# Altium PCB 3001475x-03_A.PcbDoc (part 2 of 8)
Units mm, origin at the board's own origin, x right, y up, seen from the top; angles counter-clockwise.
Board outline 100 x 72 mm, 12 copper layers (Top Layer, L2 GND, Layer 3, L4 GND, Layer 5, L6 PWR, L7 3V3, Layer 8, L9 GND, Layer 10, L11 GND, Bottom Layer), stack 1.735 mm thick; 428 components, 499 nets, 1973 pads, 1473 vias.
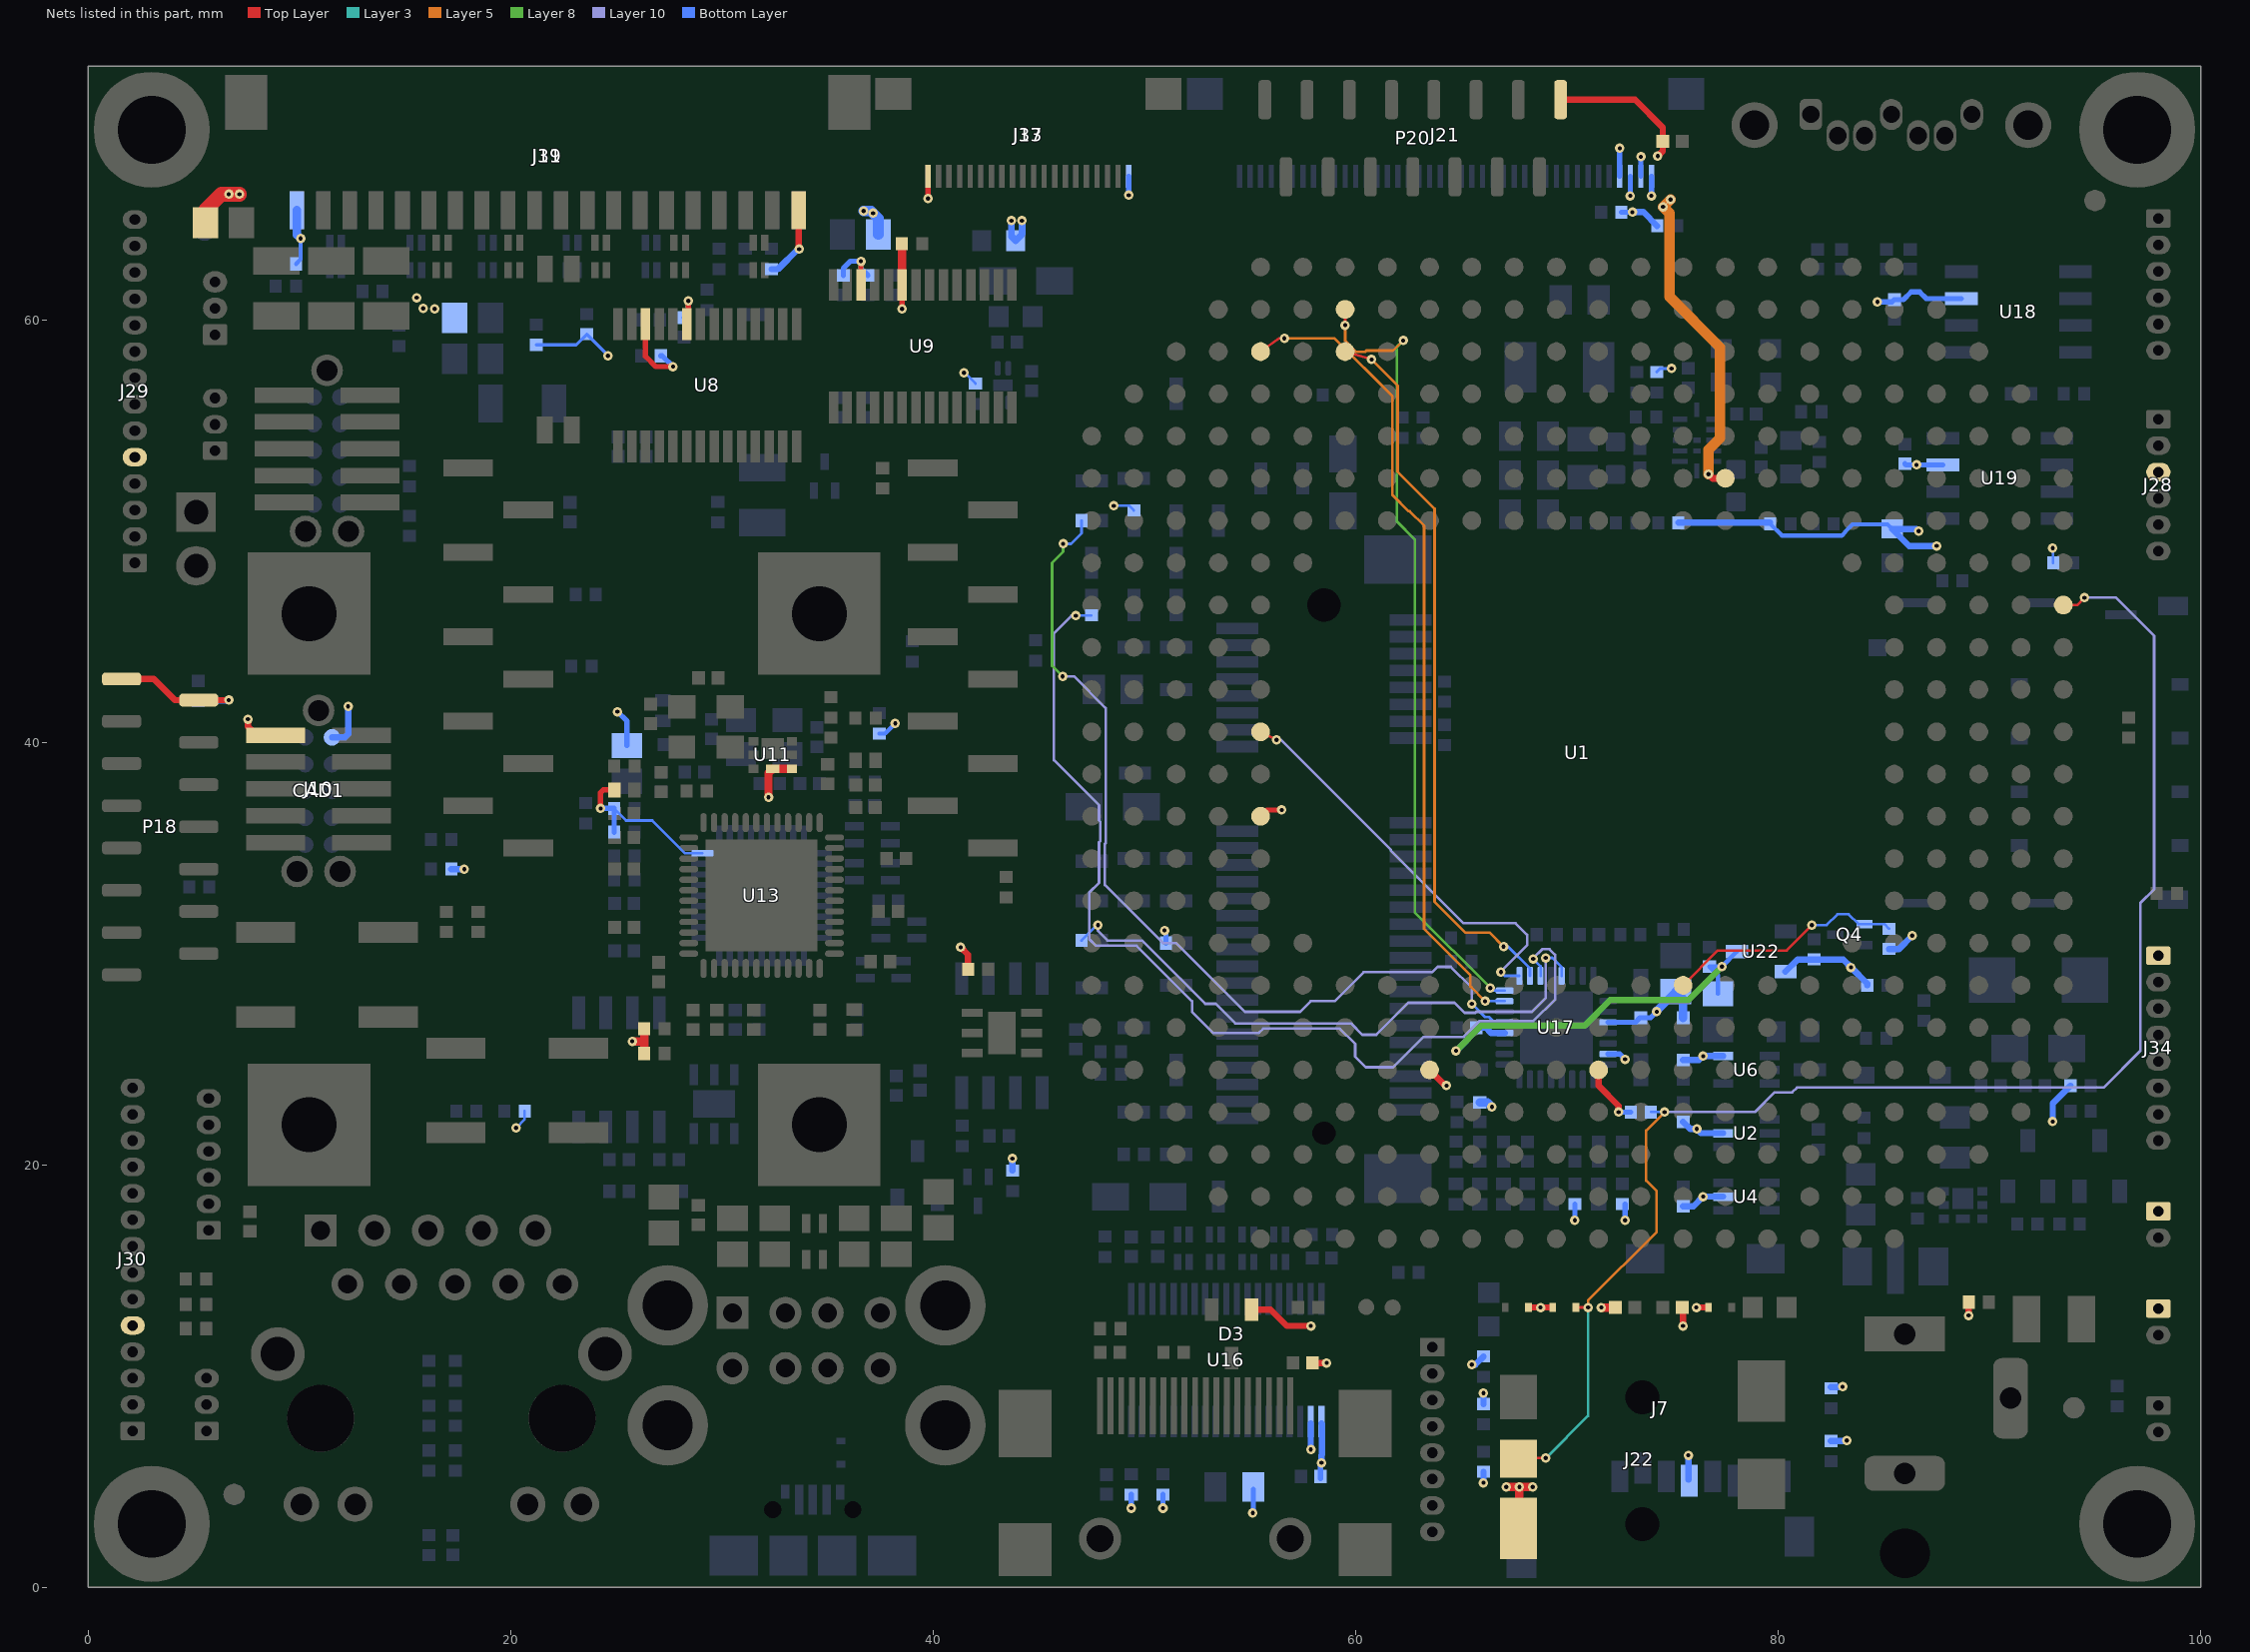
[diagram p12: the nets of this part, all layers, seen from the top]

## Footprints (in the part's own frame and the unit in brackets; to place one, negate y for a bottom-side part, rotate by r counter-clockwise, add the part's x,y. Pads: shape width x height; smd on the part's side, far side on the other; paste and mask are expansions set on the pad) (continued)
KYCON_KUSBX-AS2N [mil]
  rect 60x60 hole 35: A1(0,0)
  round 60 hole 35: A2(98.43,0) A4(275.59,0) B1(0,-103.15) B2(98.43,-103.15) B3(177.17,-103.15) B4(275.59,-103.15)
  round 60 / inner oval 60x53.15 / far side round 60 hole 35: A3(177.17,0)
  round 150 hole 93: SH1(-120.87,-209.84) SH2(-120.87,13.78) SH3(396.46,-209.84) SH4(396.46,13.78)
  body extent -171,-633 446,56, height 634
LABEL_10x10 [mm]
  silkscreen extent -5.08,-5.08 5.08,5.08
LEDM3020X130N [mm]
  rect 1.3x2.2 smd: A(-1.3,0) K(1.3,0)
  body extent -1.6,-1.1 1.6,1.1, height 1.5
MH_185_125_NP [mm]
  round 3.175 hole 3.175 unplated: 1(0,0)
  Keep-Out Layer circle w0.102: c0,0 r2.349
MODULE_CCWMX6 [mil]
  round 35 smd: A5(-590.55,905.51) A6(-511.81,905.51) A7(-433.07,905.51) A8(-354.33,905.51) A9(-275.59,905.51) A10(-196.85,905.51) A11(-118.11,905.51) A12(-39.37,905.51) A13(39.37,905.51) A14(118.11,905.51) A15(196.85,905.51) A16(275.59,905.51) A17(354.33,905.51) A18(433.07,905.51) A19(511.81,905.51) A20(590.55,905.51) AA2(-826.77,-669.29) AA3(-748.03,-669.29) AA4(-669.29,-669.29) AA5(-590.55,-669.29) AA6(-511.81,-669.29) AA7(-433.07,-669.29) AA8(-354.33,-669.29) AA9(-275.59,-669.29) AA10(-196.85,-669.29) AA11(-118.11,-669.29) AA12(-39.37,-669.29) AA13(39.37,-669.29) AA14(118.11,-669.29) AA15(196.85,-669.29) AA16(275.59,-669.29) AA17(354.33,-669.29) AA18(433.07,-669.29) AA19(511.81,-669.29) AA20(590.55,-669.29) AA21(669.29,-669.29) AA22(748.03,-669.29) AA23(826.77,-669.29) AB3(-748.03,-748.03) AB4(-669.29,-748.03) AB5(-590.55,-748.03) AB6(-511.81,-748.03) AB7(-433.07,-748.03) AB8(-354.33,-748.03) AB9(-275.59,-748.03) AB10(-196.85,-748.03) AB11(-118.11,-748.03) AB12(-39.37,-748.03) AB13(39.37,-748.03) AB14(118.11,-748.03) AB15(196.85,-748.03) AB16(275.59,-748.03) AB17(354.33,-748.03) AB18(433.07,-748.03) AB19(511.81,-748.03) AB20(590.55,-748.03) AB21(669.29,-748.03) AB22(748.03,-748.03) AC4(-669.29,-826.77) AC5(-590.55,-826.77) AC6(-511.81,-826.77) AC7(-433.07,-826.77) AC8(-354.33,-826.77) AC9(-275.59,-826.77) AC10(-196.85,-826.77) AC11(-118.11,-826.77) AC12(-39.37,-826.77) AC13(39.37,-826.77) AC14(118.11,-826.77) AC15(196.85,-826.77) AC16(275.59,-826.77) AC17(354.33,-826.77) AC18(433.07,-826.77) AC19(511.81,-826.77) AC20(590.55,-826.77) AC21(669.29,-826.77) AD5(-590.55,-905.51) AD6(-511.81,-905.51) AD7(-433.07,-905.51) AD8(-354.33,-905.51) AD9(-275.59,-905.51) AD10(-196.85,-905.51) AD11(-118.11,-905.51) AD12(-39.37,-905.51) AD13(39.37,-905.51) AD14(118.11,-905.51) AD15(196.85,-905.51) AD16(275.59,-905.51) AD17(354.33,-905.51) AD18(433.07,-905.51) AD19(511.81,-905.51) AD20(590.55,-905.51) B4(-669.29,826.77) B5(-590.55,826.77) B6(-511.81,826.77) B7(-433.07,826.77) B8(-354.33,826.77) B9(-275.59,826.77) B10(-196.85,826.77) B11(-118.11,826.77) B12(-39.37,826.77) B13(39.37,826.77) B14(118.11,826.77) B15(196.85,826.77) B16(275.59,826.77) B17(354.33,826.77) B18(433.07,826.77) B19(511.81,826.77) B20(590.55,826.77) B21(669.29,826.77) C3(-748.03,748.03) C4(-669.29,748.03) C5(-590.55,748.03) C6(-511.81,748.03) C7(-433.07,748.03) C8(-354.33,748.03) C9(-275.59,748.03) C10(-196.85,748.03) C11(-118.11,748.03) C12(-39.37,748.03) C13(39.37,748.03) C14(118.11,748.03) C15(196.85,748.03) C16(275.59,748.03) C17(354.33,748.03) C18(433.07,748.03) C19(511.81,748.03) C20(590.55,748.03) C21(669.29,748.03) C22(748.03,748.03) D2(-826.77,669.29) D3(-748.03,669.29) D4(-669.29,669.29) D5(-590.55,669.29) D6(-511.81,669.29) D7(-433.07,669.29) D8(-354.33,669.29) D9(-275.59,669.29) D10(-196.85,669.29) D11(-118.11,669.29) D12(-39.37,669.29) D13(39.37,669.29) D14(118.11,669.29) D15(196.85,669.29) D16(275.59,669.29) D17(354.33,669.29) D18(433.07,669.29) D19(511.81,669.29) D20(590.55,669.29) D21(669.29,669.29) D22(748.03,669.29) D23(826.77,669.29) E1(-905.51,590.55) E2(-826.77,590.55) E3(-748.03,590.55) E4(-669.29,590.55) E5(-590.55,590.55) E6(-511.81,590.55) E7(-433.07,590.55) E8(-354.33,590.55) E9(-275.59,590.55) E10(-196.85,590.55) E11(-118.11,590.55) E12(-39.37,590.55) E13(39.37,590.55) E14(118.11,590.55) E15(196.85,590.55) E16(275.59,590.55) E17(354.33,590.55) E18(433.07,590.55) E19(511.81,590.55) E20(590.55,590.55) E21(669.29,590.55) E22(748.03,590.55) E23(826.77,590.55) E24(905.51,590.55) F1(-905.51,511.81) F2(-826.77,511.81) F3(-748.03,511.81) F4(-669.29,511.81) F5(-590.55,511.81) F6(-511.81,511.81) F7(-433.07,511.81) F8(-354.33,511.81) F9(-275.59,511.81) F10(-196.85,511.81) F11(-118.11,511.81) F12(-39.37,511.81) F13(39.37,511.81) F14(118.11,511.81) F15(196.85,511.81) F16(275.59,511.81) F17(354.33,511.81) F18(433.07,511.81) F19(511.81,511.81) F20(590.55,511.81) F21(669.29,511.81) F22(748.03,511.81) F23(826.77,511.81) F24(905.51,511.81) G1(-905.51,433.07) G2(-826.77,433.07) G3(-748.03,433.07) G4(-669.29,433.07) G5(-590.55,433.07) G6(-511.81,433.07) G7(-433.07,433.07) G8(-354.33,433.07) G9(-275.59,433.07) G10(-196.85,433.07) G11(-118.11,433.07) G12(-39.37,433.07) G13(39.37,433.07) G14(118.11,433.07) G15(196.85,433.07) G16(275.59,433.07) G17(354.33,433.07) G18(433.07,433.07) G19(511.81,433.07) G20(590.55,433.07) G21(669.29,433.07) G22(748.03,433.07) G23(826.77,433.07) G24(905.51,433.07) H1(-905.51,354.33) H2(-826.77,354.33) H3(-748.03,354.33) H4(-669.29,354.33) H5(-590.55,354.33) H6(-511.81,354.33) H19(511.81,354.33) H20(590.55,354.33) H21(669.29,354.33) H22(748.03,354.33) H23(826.77,354.33) H24(905.51,354.33) J1(-905.51,275.59) J2(-826.77,275.59) J3(-748.03,275.59) J4(-669.29,275.59) J5(-590.55,275.59) J20(590.55,275.59) J21(669.29,275.59) J22(748.03,275.59) J23(826.77,275.59) J24(905.51,275.59) K1(-905.51,196.85) K2(-826.77,196.85) K3(-748.03,196.85) K4(-669.29,196.85) K5(-590.55,196.85) K20(590.55,196.85) K21(669.29,196.85) K22(748.03,196.85) K23(826.77,196.85) K24(905.51,196.85) L1(-905.51,118.11) L2(-826.77,118.11) L3(-748.03,118.11) L4(-669.29,118.11) L5(-590.55,118.11) L20(590.55,118.11) L21(669.29,118.11) L22(748.03,118.11) L23(826.77,118.11) L24(905.51,118.11) M1(-905.51,39.37) M2(-826.77,39.37) M3(-748.03,39.37) M4(-669.29,39.37) M5(-590.55,39.37) M20(590.55,39.37) M21(669.29,39.37) M22(748.03,39.37) M23(826.77,39.37) M24(905.51,39.37) N1(-905.51,-39.37) N2(-826.77,-39.37) N3(-748.03,-39.37) N4(-669.29,-39.37) N5(-590.55,-39.37) N20(590.55,-39.37) N21(669.29,-39.37) N22(748.03,-39.37) N23(826.77,-39.37) N24(905.51,-39.37) P1(-905.51,-118.11) P2(-826.77,-118.11) P3(-748.03,-118.11) P4(-669.29,-118.11) P5(-590.55,-118.11) P20(590.55,-118.11) P21(669.29,-118.11) P22(748.03,-118.11) P23(826.77,-118.11) P24(905.51,-118.11) R1(-905.51,-196.85) R2(-826.77,-196.85) R3(-748.03,-196.85) R4(-669.29,-196.85) R5(-590.55,-196.85) R20(590.55,-196.85) R21(669.29,-196.85) R22(748.03,-196.85) R23(826.77,-196.85) R24(905.51,-196.85) T1(-905.51,-275.59) T2(-826.77,-275.59) T3(-748.03,-275.59) T4(-669.29,-275.59) T5(-590.55,-275.59) T20(590.55,-275.59) T21(669.29,-275.59) T22(748.03,-275.59) T23(826.77,-275.59) T24(905.51,-275.59) U1(-905.51,-354.33) U2(-826.77,-354.33) U3(-748.03,-354.33) U4(-669.29,-354.33) U5(-590.55,-354.33) U6(-511.81,-354.33) U19(511.81,-354.33) U20(590.55,-354.33) U21(669.29,-354.33) U22(748.03,-354.33) U23(826.77,-354.33) U24(905.51,-354.33) V1(-905.51,-433.07) V2(-826.77,-433.07) V3(-748.03,-433.07) V4(-669.29,-433.07) V5(-590.55,-433.07) V6(-511.81,-433.07) V7(-433.07,-433.07) V8(-354.33,-433.07) V9(-275.59,-433.07) V10(-196.85,-433.07) V11(-118.11,-433.07) V12(-39.37,-433.07) V13(39.37,-433.07) V14(118.11,-433.07) V15(196.85,-433.07) V16(275.59,-433.07) V17(354.33,-433.07) V18(433.07,-433.07) V19(511.81,-433.07) V20(590.55,-433.07) V21(669.29,-433.07) V22(748.03,-433.07) V23(826.77,-433.07) V24(905.51,-433.07) W1(-905.51,-511.81) W2(-826.77,-511.81) W3(-748.03,-511.81) W4(-669.29,-511.81) W5(-590.55,-511.81) W6(-511.81,-511.81) W7(-433.07,-511.81) W8(-354.33,-511.81) W9(-275.59,-511.81) W10(-196.85,-511.81) W11(-118.11,-511.81) W12(-39.37,-511.81) W13(39.37,-511.81) W14(118.11,-511.81) W15(196.85,-511.81) W16(275.59,-511.81) W17(354.33,-511.81) W18(433.07,-511.81) W19(511.81,-511.81) W20(590.55,-511.81) W21(669.29,-511.81) W22(748.03,-511.81) W23(826.77,-511.81) W24(905.51,-511.81) Y1(-905.51,-590.55) Y2(-826.77,-590.55) Y3(-748.03,-590.55) Y4(-669.29,-590.55) Y5(-590.55,-590.55) Y6(-511.81,-590.55) Y7(-433.07,-590.55) Y8(-354.33,-590.55) Y9(-275.59,-590.55) Y10(-196.85,-590.55) Y11(-118.11,-590.55) Y12(-39.37,-590.55) Y13(39.37,-590.55) Y14(118.11,-590.55) Y15(196.85,-590.55) Y16(275.59,-590.55) Y17(354.33,-590.55) Y18(433.07,-590.55) Y19(511.81,-590.55) Y20(590.55,-590.55) Y21(669.29,-590.55) Y22(748.03,-590.55) Y23(826.77,-590.55) Y24(905.51,-590.55)
  silkscreen extent -984,-984 984,984, body extent -984,-984 984,984, height 220
MOLEX_53047-0210 [mm]
  rrect20% 0.875x1.15 hole 0.5: 1(0,0)
  oval 0.875x1.15 hole 0.5: 2(1.25,0)
  body extent -1.52,-1.15 2.73,2.05, height 4.2
MOLEX_53047-0310#1 [mm]
  rrect20% 1x1.15 hole 0.5: 1(0,0)
  oval 1x1.15 hole 0.5: 2(1.25,0) 3(2.5,0)
  body extent -1.5,-1.15 4,2.05, height 4.2
MOLEX_53047-0310#2 [mm]
  rrect20% 0.875x1.15 hole 0.5: 1(0,0)
  oval 0.875x1.15 hole 0.5: 2(1.25,0) 3(2.5,0)
  body extent -1.5,-1.15 4,2.05, height 4.2
MOLEX_53047-0610 [mm]
  rrect20% 0.875x1.15 hole 0.5: 1(0,0)
  oval 0.875x1.15 hole 0.5: 2(1.25,0) 3(2.5,0) 4(3.75,0) 5(5,0) 6(6.25,0)
  body extent -1.5,-1.15 7.75,2.05, height 4.2
MOLEX_53047-0810#1 [mm]
  rect 0.875x1.15 hole 0.5: 1(0,0)
  oval 0.875x1.15 hole 0.5: 2(1.25,0) 3(2.5,0) 4(3.75,0) 5(5,0) 6(6.25,0) 7(7.5,0) 8(8.75,0)
  body extent -1.5,-1.15 10.25,2.05, height 4.2
MOLEX_53047-0810#2 [mm]
  rrect20% 0.875x1.15 hole 0.5: 1(0,0)
  oval 0.875x1.15 hole 0.5: 2(1.25,0) 3(2.5,0) 4(3.75,0) 5(5,0) 6(6.25,0) 7(7.5,0) 8(8.75,0)
  body extent -1.5,-1.15 10.25,2.05, height 4.2
MOLEX_53047-1410 [mm]
  rrect20% 0.875x1.15 hole 0.5: 1(0,0)
  oval 0.875x1.15 hole 0.5: 2(1.25,0) 3(2.5,0) 4(3.75,0) 5(5,0) 6(6.25,0) 7(7.5,0) 8(8.75,0) 9(10,0) 10(11.25,0) 11(12.5,0) 12(13.75,0) 13(15,0) 14(16.25,0)
  body extent -1.5,-1.15 17.75,2.05, height 4.2
MOLEX_78727-0001 [mm]
  rect 0.8x0.6 smd: 1(0.33,4.38) 2(0.33,1.84) 3(0.33,-0.7) 4(0.33,-3.24) 5(-7.29,4.38) 6(-7.29,1.84) 7(-7.29,-0.7) 8(-7.29,-3.24)
  rect 0.85x0.8 smd: 9(-13.99,-4.98)
  rect 1.5x0.42 smd: 10(-2.47,-6.54) 12(-6.35,7.11) 13(-12.21,7.11) 14(-12.21,-7.11) 15(-6.35,-7.11)
  rect 1.4x0.87 smd: 11(0,6.95) 16(0,-6.95)
  body extent -14.53,-7.26 0.69,7.27, height 1.4
MOLEX_500873-0806 [mm]
  rect 0.8x1.5 smd: 1(0,0) 2(1.1,-0.4) 3(2.2,0) 4(3.3,0.2) 5(4.4,0) 6(5.5,0.2) 7(6.6,0) 8(7.7,0)
  rect 1.8x1.4 smd: 9(1.2,-10.3) 10(6.9,-10.3)
  rect 1.4x1.9 smd: 11(8.5,2.85) 12(-4.65,3.85)
  body extent -5.05,-10.7 8.95,4.5, height 1.87
omron_xf2m-2015-1a [mm]
  rect 0.25x1.1 smd: 1(-4.75,1.95) 2(-4.25,1.95) 3(-3.75,1.95) 4(-3.25,1.95) 5(-2.75,1.95) 6(-2.25,1.95) 7(-1.75,1.95) 8(-1.25,1.95) 9(-0.75,1.95) 10(-0.25,1.95) 11(0.25,1.95) 12(0.75,1.95) 13(1.25,1.95) 14(1.75,1.95) 15(2.25,1.95) 16(2.75,1.95) 17(3.25,1.95) 18(3.75,1.95) 19(4.25,1.95) 20(4.75,1.95)
  rect 1.7x1.5 smd: M1(6.4,-1.95) M2(-6.4,-1.95)
  body extent -7.05,-2.9 7.05,3.3, height 2.18
OMRON_XF2M-4015-1A [mm]
  rect 0.25x1.1 smd: 1(-9.75,1.95) 2(-9.25,1.95) 3(-8.75,1.95) 4(-8.25,1.95) 5(-7.75,1.95) 6(-7.25,1.95) 7(-6.75,1.95) 8(-6.25,1.95) 9(-5.75,1.95) 10(-5.25,1.95) 11(-4.75,1.95) 12(-4.25,1.95) 13(-3.75,1.95) 14(-3.25,1.95) 15(-2.75,1.95) 16(-2.25,1.95) 17(-1.75,1.95) 18(-1.25,1.95) 19(-0.75,1.95) 20(-0.25,1.95) 21(0.25,1.95) 22(0.75,1.95) 23(1.25,1.95) 24(1.75,1.95) 25(2.25,1.95) 26(2.75,1.95) 27(3.25,1.95) 28(3.75,1.95) 29(4.25,1.95) 30(4.75,1.95) 31(5.25,1.95) 32(5.75,1.95) 33(6.25,1.95) 34(6.75,1.95) 35(7.25,1.95) 36(7.75,1.95) 37(8.25,1.95) 38(8.75,1.95) 39(9.25,1.95) 40(9.75,1.95)
  rect 1.7x1.5 smd: M1(11.4,-1.95) M2(-11.4,-1.95)
  body extent -12.05,-2.9 12.05,3.3, height 2.18
OSC210P320X250X90-4N [mm]
  rect 1.25x1.1 smd: 1(-1.15,-0.95)
  rect 1.3x1.1 smd: 2(1.15,-0.95) 3(1.15,0.95) 4(-1.15,0.95)
  body extent -1.63,-1.3 1.62,1.3, height 0.6
PCBNUMBER [mm]
QFN50P500X500X100-33CN [mm]
  rrect50% 0.85x0.3 smd: 1(-2.45,1.75) 2(-2.45,1.25) 3(-2.45,0.75) 4(-2.45,0.25) 5(-2.45,-0.25) 6(-2.45,-0.75) 7(-2.45,-1.25) 8(-2.45,-1.75) 17(2.45,-1.75) 18(2.45,-1.25) 19(2.45,-0.75) 20(2.45,-0.25) 21(2.45,0.25) 22(2.45,0.75) 23(2.45,1.25) 24(2.45,1.75)
  rrect50% 0.3x0.85 smd: 9(-1.75,-2.45) 10(-1.25,-2.45) 11(-0.75,-2.45) 12(-0.25,-2.45) 13(0.25,-2.45) 14(0.75,-2.45) 15(1.25,-2.45) 16(1.75,-2.45) 25(1.75,2.45) 26(1.25,2.45) 27(0.75,2.45) 28(0.25,2.45) 29(-0.25,2.45) 30(-0.75,2.45) 31(-1.25,2.45) 32(-1.75,2.45)
  rect 3.45x3.45 smd: 33(0,0)
  body extent -2.5,-2.5 2.5,2.5, height 1.01
QFN50P600X600X100-37AN [mm]
  rrect35% 1.05x0.3 smd: 1(-2.8,2) 9(-2.8,-2) 19(2.8,-2) 27(2.8,2)
  rrect25% 1.1x0.3 smd: 2(-2.8,1.5) 3(-2.8,1) 4(-2.8,0.5) 5(-2.8,0) 6(-2.8,-0.5) 7(-2.8,-1) 8(-2.8,-1.5) 20(2.8,-1.5) 21(2.8,-1) 22(2.8,-0.5) 23(2.8,0) 24(2.8,0.5) 25(2.8,1) 26(2.8,1.5)
  rrect35% 0.3x1.05 smd: 10(-2,-2.8) 18(2,-2.8) 28(2,2.8) 36(-2,2.8)
  rrect25% 0.3x1.1 smd: 11(-1.5,-2.8) 12(-1,-2.8) 13(-0.5,-2.8) 14(0,-2.8) 15(0.5,-2.8) 16(1,-2.8) 17(1.5,-2.8) 29(1.5,2.8) 30(1,2.8) 31(0.5,2.8) 32(0,2.8) 33(-0.5,2.8) 34(-1,2.8) 35(-1.5,2.8)
  rect 3.8x3.8 smd: 37(0,0)
  body extent -3.05,-3.05 3.05,3.05, height 1.01
QFN50P700X700X100-49N [mm]
  oval 0.9x0.3 smd: 1(-3.45,2.75) 2(-3.45,2.25) 3(-3.45,1.75) 4(-3.45,1.25) 5(-3.45,0.75) 6(-3.45,0.25) 7(-3.45,-0.25) 8(-3.45,-0.75) 9(-3.45,-1.25) 10(-3.45,-1.75) 11(-3.45,-2.25) 12(-3.45,-2.75) 25(3.45,-2.75) 26(3.45,-2.25) 27(3.45,-1.75) 28(3.45,-1.25) 29(3.45,-0.75) 30(3.45,-0.25) 31(3.45,0.25) 32(3.45,0.75) 33(3.45,1.25) 34(3.45,1.75) 35(3.45,2.25) 36(3.45,2.75)
  oval 0.3x0.9 smd: 13(-2.75,-3.45) 14(-2.25,-3.45) 15(-1.75,-3.45) 16(-1.25,-3.45) 17(-0.75,-3.45) 18(-0.25,-3.45) 19(0.25,-3.45) 20(0.75,-3.45) 21(1.25,-3.45) 22(1.75,-3.45) 23(2.25,-3.45) 24(2.75,-3.45) 37(2.75,3.45) 38(2.25,3.45) 39(1.75,3.45) 40(1.25,3.45) 41(0.75,3.45) 42(0.25,3.45) 43(-0.25,3.45) 44(-0.75,3.45) 45(-1.25,3.45) 46(-1.75,3.45) 47(-2.25,3.45) 48(-2.75,3.45)
  rect 5.3x5.3 smd: 49(0,0)
  body extent -3.57,-3.57 3.57,3.57, height 1.01
QFN_MPS_MP2316 [mm]
  rect 0.75x0.25 smd: 1(-0.8,1)
  rect 0.7x0.25 smd: 2(-0.8,0.5) 3(-0.8,0) 4(-0.8,-0.5) 5(-0.8,-1) 7(0.8,-1) 8(0.8,-0.5) 9(0.8,0) 10(0.8,0.5) 11(0.8,1)
  rect 0.25x0.7 smd: 6(0,-1.45) 12(0,1.45)
  rect 0.35x0.25 smd: 13(0,0.5) 14(0,0)
  body extent -1,-1.5 1,1.5, height 1.01
RESC1005X40N#1 [mm]
  rect 0.57x0.62 smd: 1(-0.48,0) 2(0.48,0)
  body extent -0.5,-0.25 0.5,0.25, height 0.4
RESC1005X40N#2 [mm]
  rect 0.57x0.62 smd mask+0.05: 1(-0.48,0) 2(0.48,0)
  body extent -0.5,-0.25 0.5,0.25, height 0.4
RESC1609X55N#1 [mm]
  rect 0.9x1 smd: 1(-0.8,0) 2(0.8,0)
  body extent -0.87,-0.48 0.87,0.48, height 0.55
RESC1609X55N#2 [mm]
  rect 0.9x1 smd mask+0.05: 1(-0.8,0) 2(0.8,0)
  body extent -0.87,-0.48 0.87,0.48, height 0.55
RESC2013X70N [mm]
  rect 1.05x1.4 smd: 1(-0.95,0) 2(0.95,0)
  body extent -1.1,-0.67 1.1,0.68, height 0.7
SAMTEC_FTSH-105-01-F-DV [mil]
  rect 110x29 smd: 1(-80,100) 2(80,100) 3(-80,50) 4(80,50) 5(-80,0) 6(80,0) 7(-80,-50) 8(80,-50) 9(-80,-100) 10(80,-100)
  body extent -115,-207 115,208, height 325
SAMTEC_SMM-110-02-F-S [mm]
  rect 0.8x2.35 smd: 1(-9,-1.425) 2(-7,1.425) 3(-5,-1.425) 4(-3,1.425) 5(-1,-1.425) 6(1,1.425) 7(3,-1.425) 8(5,1.425) 9(7,-1.425) 10(9,1.425)
  body extent -10,-1 10,1, height 7.37
SOD3716X135N [mm]
  rect 1x0.8 smd: A(-1.8,0) K(1.8,0)
  body extent -1.95,-0.9 1.95,0.9, height 1.36
SODFL1006X43N12 [mm]
  rect 0.32x0.43 smd: 1(-0.55,0) 2(0.55,0)
  body extent -0.58,-0.33 0.58,0.33, height 0.4
SOIC127P600X175-8N [mm]
  rect 0.6x1.55 smd: 1(-1.905,-2.7) 2(-0.635,-2.7) 3(0.635,-2.7) 4(1.905,-2.7) 5(1.905,2.7) 6(0.635,2.7) 7(-0.635,2.7) 8(-1.905,2.7)
  body extent -2.5,-3.1 2.5,3.1, height 1.75
SON50P120X160X60-5T55X91N [mm] "Small Outline No-Lead (SON with Tab), 0.50 mm pitch; 4 pin, 1.20 mm L X 1.60 mm W X 0.60 mm H body"
  rrect52% 0.67x0.27 smd mask+0.051: 1(-0.81,0.25) 2(-0.81,-0.25) 3(0.81,-0.25) 4(0.81,0.25)
  rect 0.55x0.91 smd paste-0.099 mask+0.051: 5(0,0)
  body extent -0.85,-0.6 0.85,0.6, height 0.6
SON95P300X300X80-7N [mm]
  rect 0.4x1 smd: 1(-0.95,-1.4) 2(0,-1.4) 3(0.95,-1.4) 4(0.95,1.4) 5(0,1.4) 6(-0.95,1.4)
  rect 2x1.3 smd: 7(0,0)
  body extent -1.58,-1.58 1.58,1.58, height 0.8
SOP50P640X120-38N [mm]
  rect 1.5x0.3 smd: 1(-2.9,4.5) 2(-2.9,4) 3(-2.9,3.5) 4(-2.9,3) 5(-2.9,2.5) 6(-2.9,2) 7(-2.9,1.5) 8(-2.9,1) 9(-2.9,0.5) 10(-2.9,0) 11(-2.9,-0.5) 12(-2.9,-1) 13(-2.9,-1.5) 14(-2.9,-2) 15(-2.9,-2.5) 16(-2.9,-3) 17(-2.9,-3.5) 18(-2.9,-4) 19(-2.9,-4.5) 20(2.9,-4.5) 21(2.9,-4) 22(2.9,-3.5) 23(2.9,-3) 24(2.9,-2.5) 25(2.9,-2) 26(2.9,-1.5) 27(2.9,-1) 28(2.9,-0.5) 29(2.9,0) 30(2.9,0.5) 31(2.9,1) 32(2.9,1.5) 33(2.9,2) 34(2.9,2.5) 35(2.9,3) 36(2.9,3.5) 37(2.9,4) 38(2.9,4.5)
  body extent -3.3,-4.9 3.3,4.9, height 1.1
SOP65P640X120-28N [mm]
  rect 0.45x1.5 smd: 1(-4.225,-2.9) 2(-3.575,-2.9) 3(-2.925,-2.9) 4(-2.275,-2.9) 5(-1.625,-2.9) 6(-0.975,-2.9) 7(-0.325,-2.9) 8(0.325,-2.9) 9(0.975,-2.9) 10(1.625,-2.9) 11(2.275,-2.9) 12(2.925,-2.9) 13(3.575,-2.9) 14(4.225,-2.9) 15(4.225,2.9) 16(3.575,2.9) 17(2.925,2.9) 18(2.275,2.9) 19(1.625,2.9) 20(0.975,2.9) 21(0.325,2.9) 22(-0.325,2.9) 23(-0.975,2.9) 24(-1.625,2.9) 25(-2.275,2.9) 26(-2.925,2.9) 27(-3.575,2.9) 28(-4.225,2.9)
  body extent -4.9,-3.3 4.9,3.3, height 1.21
SOT65P210X110-5N [mm]
  rect 0.4x0.95 smd: 1(-0.65,-1.1) 2(0,-1.1) 3(0.65,-1.1) 4(0.65,1.1) 5(-0.65,1.1)
  body extent -1.07,-1.2 1.07,1.2, height 1.11
SOT65P210X110-6N [mm]
  rect 0.4x0.95 smd: 1(-0.65,-1.1) 2(0,-1.1) 3(0.65,-1.1) 4(0.65,1.1) 5(0,1.1) 6(-0.65,1.1)
  body extent -1.07,-1.2 1.07,1.2, height 1.11
SOT95P240X110-3N [mm]
  rect 0.7x1.1 smd: 1(-0.95,-1.2) 2(0.95,-1.2) 3(0,1.2)
  body extent -1.56,-1.35 1.56,1.35, height 1.11
SOT95P240X110_AXK-3N [mm]
  rect 0.65x1.05 smd: A(-0.95,-1.15) K(0,1.15) X(0.95,-1.15)
  body extent -1.56,-1.35 1.56,1.35, height 1.11
SOT95P240X110_GSD-3N [mm]
  rect 0.65x1.05 smd: D(0,1.15) G(-0.95,-1.15) S(0.95,-1.15)
  body extent -1.56,-1.35 1.56,1.35, height 1.11
SOTFL50P160X80_GSD-3N [mm]
  rect 0.4x0.77 smd: D(0,0.69) G(-0.5,-0.69) S(0.5,-0.69)
  body extent -0.85,-0.85 0.85,0.85, height 0.8
SW_KSC221J [mm]
  rect 1x2.8 smd: 1(2,2.9) 2(2,-2.9) 3(-2,2.9) 4(-2,-2.9)
  body extent -3.1,-3.4 3.1,3.4, height 3.5
SW_TDA02 [mm]
  rect 1.27x0.76 smd: 1(-3.81,0.635) 2(-3.81,-0.635) 3(3.81,-0.635)
  rect 1.27x0.74 smd: 4(3.81,0.635)
  body extent -3.12,-1.84 3.13,1.84, height 2.3
TC_TC2050-IDC-NL [mil]
  round 31 smd paste-50: 1(-100,-25) 2(-50,-25) 3(0,-25) 4(50,-25) 5(100,-25) 6(100,25) 7(50,25) 8(0,25) 9(-50,25) 10(-100,25)
  round 59 hole 39 unplated: MT1(-150,0) MT2(150,40) MT3(150,-40)
TP0762 [mil] "30mil SMT Round Testpoint"
  round 30 smd paste-100: 1(0,0)
XTAL_C3E-3427 [mm]
  rect 1.4x1.15 smd: 1(-1.1,-0.8) 2(1.1,-0.8) 3(1.1,0.8) 4(-1.1,0.8)
  body extent -1.7,-1.35 1.7,1.35, height 0.75

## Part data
C1 C9 C34 C35 C36: library part 1001196, "CAP TANT 100UF 6.3V 20% 1206", Manufacturer=Rohm, Manufacturer_Part_Number=TCTAL0J107M8R, Package_Type=3216, Tolerance=20%, Voltage=6.3V
C2 C11 C12 C42 C49 C56 C57 C60 C67 C69 C71 C72 C98: library part 1001168, "CAP CER 10UF 10V 20% X5R 0402", Manufacturer=Samsung, Manufacturer_Part_Number=CL05A106MP5NUNC, Package_Type=0402, Temp_Coef=X5R, Tolerance=20%, Voltage=10V
C3 C62 C65 C87 C88 C91 C92 C93 C94 C104: library part 1001167, "CAP CER 1UF 10V 10% X5R 0402", Manufacturer=Murata, Manufacturer_Part_Number=GRM155R61A105KE15D, Package_Type=0402, Temp_Coef=X5R, Tolerance=10%, Voltage=10V
C4 C5 C6 C7 C10 C13 C18 C19 C20 C21 C22 C23 C24 C25 C26 C27 C29 C31 C32 C33 C37 C38 C39 C41 C43 C44 C45 C46 C47 C48 C50 C51 C52 C53 C54 C55 C58 C59 C61 C66 C68 C70 C73 C74 C75 C76 C77 C78 C79 C81 C82 C83 C84 C85 C86 C89 C90 C95 C96 C97 C99 C100 C101 C105 C106 C107 C118: library part 1000006, "CAP 100nF 16V 10% X7R 0402", Manufacturer=Murata, Manufacturer_Part_Number=GRM155R71C104KA88D, Package_Type=0402, Tolerance=10
C8 C102 C103 C112: library part 1000998, "CAP CER 22UF 10V 20% X5R 0603", Manufacturer=Samsung, Manufacturer_Alt_1="TDK Corporation", Manufacturer_Alt_1_Part_Number=C1608X5R1A226M080AC, Manufacturer_Part_Number=CL10A226MP8NUNE, Package_Type=0603, Temp_Coef=X5R, Tolerance=20, Voltage=10V
C14 C15 C16 C17: library part 1001165, "CAP CER 10000PF 16V 10% X7R 0402", Manufacturer=Kemet, Manufacturer_Part_Number=C0402C103K4RACTU, Package_Type=0402, Temp_Coef=X7R, Tolerance=10%, Voltage=16V
C28 C30: library part 1001166, "CAP CER 22PF 50V 5% NP0 0402", Manufacturer=Murata, Manufacturer_Part_Number=GRM1555C1H220JA01D, Package_Type=0402, Temp_Coef="C0G, NP0", Tolerance=5%, Voltage=50V
C40 C80: library part 1000500, "CAP CER 4.7UF 25V 10% X5R 0805", Manufacturer=Murata, Manufacturer_Part_Number=GRM21BR61E475KA12L, Package_Type=0805, Temp_Coef=X5R, Tolerance=10%, Voltage=25V
C63 C64: library part 1002646, "CAP CER 33PF 50V C0G/NP0 0402", Manufacturer=Murata, Manufacturer_Part_Number=GCM1555C1H330JA16D, Package_Type=0402, Tolerance=5%, Voltage=50
C108: library part 1000007, "CAP 47pF 50V 5% NP0 0402", Manufacturer=Murata, Manufacturer_Alt_1="AVX Corporation", Manufacturer_Alt_1_Part_Number=04025A470JAT2A, Manufacturer_Part_Number=GRM1555C1H470JA01D, Package_Type=0402, Temp_Coef="C0G, NP0"
C109: library part 1000110, "CAP CER 1UF 25V 10% X5R 0603", Manufacturer=Murata, Manufacturer_Alt_1="AVX Corporation", Manufacturer_Alt_1_Part_Number=TMK107BJ105KA-T, Manufacturer_Part_Number=GRM188R61E105KA12D, Package_Type=0603, Temp_Coef=X5R, Tolerance=10%, Voltage=25V
C110: library part 1000512, "CAP CER 0.015UF 16V 10% X7R 0402", Manufacturer=Murata, Manufacturer_Part_Number=GRM155R71C153KA01D, Package_Type=0402, Temp_Coef=X7R, Tolerance=10%, Voltage=16V
C111: library part 1000501, "CAP CER 47UF 6.3V 20% X5R 0805", Manufacturer="Taiyo Yuden", Manufacturer_Part_Number=JMK212BJ476MG-T, Package_Type=0805, Temp_Coef=X5R, Tolerance=20%, Voltage=6.3V
C113: library part 1000918, "CAP CER 0.1UF 50V 10% X7R 0402", Manufacturer="TDK Corporation", Manufacturer_Part_Number=C1005X7R1H104K050BB, Package_Type=0402, Temp_Coef=X7R, Tolerance=10%, Voltage=50V
C114: library part 1000566, "CAP CER 100UF 10V 20% X5R 1206", Manufacturer="TDK Corporation", Manufacturer_Part_Number=C3216X5R1A107M, Package_Type=1206, Temp_Coef=X5R, Tolerance=20%, Voltage=10V
C115 C116 C117 C119: library part 1000111, "CAP CER 10UF 16V 10% X5R 0805", Manufacturer=Murata, Manufacturer_Part_Number=GRM21BR61C106KE15L, Package_Type=0805, Temp_Coef=X5R, Tolerance=10, Voltage=16V
CAD1 CAD2: library part CAD0066, "CBL PLUG-OF-NAILS 10-PIN", Package_Type=SMT
D1 D4 D11: library part 1001189, "LED GREEN 573NM 1208 SMD", Manufacturer=Dialight, Package_Type=SMT
D2: library part 1001494, "DIODE ZENER 5.1V 500MW SOD123", Manufacturer="On Semiconductor", Package_Type=SOD123
D3: library part 1001169, "DIODE SCHOTTKY 30V 0.2A SOT23-3", Manufacturer="Fairchild Semiconductor", Package_Type=SMT
D5: library part 1001188, "LED YELLOW 588NM 1208 SMD", Manufacturer=Dialight, Package_Type=SMT
D6: library part 1001190, "LED RED 653NM 20MA 1208 SMD", Manufacturer=Dialight, Package_Type=SMT
D7 D8 D9 D10: library part 1001264, "TVS DIODE 5VWM SOD923", Manufacturer="On Semiconductor", Package_Type=SMT
FIDUCIAL1 FIDUCIAL2 FIDUCIAL3 FIDUCIAL4 FIDUCIAL5 FIDUCIAL6 FIDUCIAL11 FIDUCIAL12 FIDUCIAL13 FIDUCIAL14: library part CAD0023, "40 Mil Round Fiducial", Package_Type=SMT
FIL1: library part 1001918, "DNF 2 MHZ -1000 MHZ SMD", Manufacturer="Panasonic - ECG", Manufacturer_Part_Number=ELKEA333FA, Package_Type=SMT
H1 H2 H3 H4: library part CAD0006, "NPTH for Tooling, 0.125in dia.", Package_Type=TH
J1: library part 1001105, "DC Power Jack", Manufacturer="Bobbintron Electrical Corp", Package_Type=TH
J2 J4 J5: library part 1001136, "CONN HEADER 2POS 1.25MM VERT TIN", Manufacturer=Molex, Manufacturer_Part_Number=53047-0210, Package_Type=TH
J3 J9 J25: library part 1001183, "CONN HEADER 3POS 1.25MM VERT TIN", Manufacturer=Molex, Manufacturer_Part_Number=53047-0310, Package_Type=TH
J7: library part 1001118, "CONN TRANSFLSH R/A PUSH-PUSH SMD", Manufacturer=Molex, Package_Type=SMT
J8: library part 1001115, "CONN PLUG SATA 7PS VERT PCB GOLD", Manufacturer=3M, Package_Type=TH
J10 J11: library part 1000034, "CONN HEADER 10POS DUAL .05\" SMD", Manufacturer=Samtec, Package_Type=SMT
J12: library part 1001130, "SMCONN,MINI PCI EXP, 6.8MM HT", Manufacturer=Foxconn, Manufacturer_Part_Number=AS0B226-S68Q-7H, Package_Type=SMT
J13: library part 1001966, "CONN MAGJACK 1PORT 1000 BASE-T, -40/85°C", Manufacturer=XMultiple, Manufacturer_Part_Number=XMG-1108D1006-1, Package_Type=TH
J14: library part 1001120, "MEMORY CARD 6POS PUSH/PULL SMD", Manufacturer=Molex, Package_Type=SMT
J15: library part 1001121, "USB Stacked Dual A type", Manufacturer=KYCON, Package_Type=TH
J16: library part 1001117, "CONN RECEPT MICRO-USB TYPE AB R/A", Manufacturer=KYCON, Package_Type=SMT
J17 J33: library part 1001145, "CONN FPC 20POS 0.5MM PITCH SMD", Manufacturer=Omron, Manufacturer_Part_Number=XF2M-2015-1A, Package_Type=SMT
J18: library part 1001128, "CONN HEADER 2POS .100\" SGL GOLD", Manufacturer=Samtec, Manufacturer_Part_Number=TSW-102-07-G-S, Package_Type=TH
J19 J31: library part 1001132, "CONN HEADER 20POS 1.25MM R/A SMD", Manufacturer=Hirose, Manufacturer_Part_Number=DF14A-20P-1.25H, Package_Type=SMT
J21: library part 1001144, "CONN FPC 40POS 0.5MM PITCH SMD", Manufacturer=Omron, Manufacturer_Part_Number=XF2M-4015-1A, Package_Type=SMT
J22: library part 1001133, "CONN JACK STEREO 5POS 3.5MM SMD", Manufacturer="CUI Inc.", Manufacturer_Part_Number=SJ1-3515-SMT, Package_Type=SMT
J23 J24: library part 1001495, "CONN RCPT 2MM 10POS SMD", Manufacturer=Samtec, Package_Type=SMT
J26 J34: library part 1001139, "CONN HEADER 8POS 1.25MM VERT TIN", Manufacturer=Molex, Manufacturer_Part_Number=53047-0810, Package_Type=TH
J27 J28 J32: library part 1001138, "CONN HEADER 6POS 1.25MM VERT TIN", Manufacturer=Molex, Manufacturer_Part_Number=53047-0610, Package_Type=TH
J29 J30: library part 1001140, "CONN HEADER 14POS 1.25MM STR TIN", Manufacturer=Molex, Manufacturer_Part_Number=53047-1410, Package_Type=TH
L1: library part 1001912, "FIXED IND 1.5UH 4.5A 42 MOHM SMD", Manufacturer=Bourns, Manufacturer_Part_Number=SRP4020TA-1R5M, Package_Type=SMT
L2 L3 L4 L5 L18 L19 L20 L21 L22 L23 L24 L25: library part 1001175, "FERRITE BEAD 120 OHM .35A 0402", Manufacturer="Wurth Electronics Inc", Manufacturer_Part_Number=7427927112, Package_Type=0402
L6 L7 L9 L12 L13 L15 L17 L26 L27 L28 L29 L35 L45: library part 1001174, "FERRITE BEAD 220 OHM 2.0A 0805", Manufacturer="Wurth Electronics Inc", Manufacturer_Part_Number=742792022, Package_Type=0805
L8 L10 L11 L14 L16: library part 1001173, "CHOKE COM MODE 120 OHM .37A", Manufacturer="Wurth Electronics Inc", Package_Type=SMT
L30 L31 L32 L33 L34 L36 L37 L38 L39 L40 L41 L42 L43 L44: library part 1001014, "CHOKE COIL COMMON MODE 150MA SMD", Manufacturer=Murata, Manufacturer_Part_Number=DLP11SN900HL2L, Package_Type=SMT
LBL1: library part 1002170, "LBL,Poly White Blank 0.40x0.40", Manufacturer=3M, Manufacturer_Part_Number=TAAE-014000, Package_Type=NONE
P1: library part 1001123, "HDMI RECEPTACLE, SMT", Manufacturer=KYCON, Package_Type=SMT
P18 P20: library part 1001866, "CONN FFC FPC VERT 15POS 1MM SMD", Manufacturer=FCI, Package_Type=SMT
PCB1: library part 3000137, "PCB CCWM6_SBC_v0.3"
Q1 Q3: library part 1001204, "TRANS GP SS PNP 40V SOT23", Manufacturer="On Semiconductor", Package_Type=SOT23
Q2 Q4 Q5: library part 1000715, "MOSFET N-CH 60V 115MA SOT-523F", Manufacturer="Fairchild Semiconductor", Package_Type=SOT523F
R1 R2 R3 R42 R43 R48: library part 1000466, "RES 49.9 OHM 1/10W 1% 0402 SMD", Manufacturer="Panasonic - ECG", Manufacturer_Part_Number=ERJ-2RKF49R9X, Package_Type=0402, Power=100, Tolerance=1%
R4 R5 R6 R20 R24 R25 R44 R47 R51 R52 R77 R80 R81 R82 R84 R95 R96 R97 R98 R99 R100 R101 R102 R103 R105 R106 R107 R108 R111 R112 R113 R114 R115 R123 R129 R130 R131 R134 R135 R136 R141 R149 R150 R151 R152 R155 R156 R204 R205 R206 R207 R208 R257 R258 R259 R298 R299: library part 1000076, "RES 0.0 OHM 1/10W 0402 SMD", Manufacturer="Panasonic - ECG", Manufacturer_Part_Number=ERJ-2GE0R00X, Package_Type=0402, Power=10
R7 R13 R23 R31 R32 R33 R34 R36 R53 R55 R58 R60 R61 R62 R63 R64 R65 R66 R69 R72 R76 R78 R91 R92 R93 R117 R118 R122 R125 R126 R127 R128 R145 R146 R147 R153 R154: library part 1000537, "RES 10.0K OHM 1/10W 1% 0402 SMD", Manufacturer="Panasonic - ECG", Manufacturer_Part_Number=ERJ-2RKF1002X, Package_Type=0402, Power=100, Tolerance=1%
R8 R35 R46: library part 1000467, "RES 100 OHM 1/10W 1% 0402 SMD", Manufacturer="Panasonic - ECG", Manufacturer_Part_Number=ERJ-2RKF1000X, Package_Type=0402, Tolerance=1%
R9 R10 R16 R17 R18 R19 R22 R28 R29 R41 R50 R54 R56 R57 R59: library part 1000079, "RES 1.00K OHM 1/10W 1% 0402 SMD", Manufacturer="Panasonic - ECG", Manufacturer_Part_Number=ERJ-2RKF1001X, Package_Type=0402, Power=10
R11: library part 1001323, "RES 270 OHM 1/2W 5% 0805 SMD", Manufacturer="Panasonic - ECG", Manufacturer_Part_Number=ERJ-P06J271V, Package_Type=0805, Power=500, Tolerance=5%
R12: library part 1001154, "RES 220 OHM 1/16W 1% 0402 SMD", Manufacturer=Yageo, Manufacturer_Part_Number=RC0402FR-07220RL, Package_Type=0402, Tolerance=1%
R14 R137 R138: library part 1000701, "RES 470K OHM 1/10W 1% 0402 SMD", Manufacturer="Panasonic - ECG", Manufacturer_Part_Number=ERJ-2RKF4703X, Package_Type=0402, Power=100, Tolerance=1%
R15: library part 1001150, "RES 316K OHM 1/10W 1% 0603 SMD", Manufacturer=Yageo, Manufacturer_Part_Number=RC0603FR-07316KL, Package_Type=0603, Power=100, Tolerance=1%
R21 R83: library part 1000208, "RES 0.0 OHM 1/10W 0603", Manufacturer="Panasonic - ECG", Manufacturer_Part_Number=ERJ-3GEY0R00V, Package_Type=0603, Voltage=75V
R26 R27 R68 R71 R73 R74 R88 R90: library part 1001155, "RES 47.0K OHM 1/16W 1% 0402 SMD", Manufacturer="Vishay Dale", Manufacturer_Part_Number=CRCW040247K0FKED, Package_Type=0402, Tolerance=1%
R30: library part 1001149, "RES 22.1K OHM 1/16W 1% 0402 SMD", Manufacturer="Vishay Dale", Manufacturer_Part_Number=CRCW040222K1FKED, Package_Type=0402, Power=0.063, Tolerance=±100ppm/°C
R37 R40 R75 R85 R87 R132: library part 1000038, "RES 4.7K OHM 1/10W 5% 0402 SMD", Manufacturer="Panasonic - ECG", Manufacturer_Part_Number=ERJ-2GEJ472X, Package_Type=0402, Power=100, Tolerance=5
R38 R45: library part 1000465, "RES 150 OHM 1/10W 1% 0402 SMD", Manufacturer="Panasonic - ECG", Manufacturer_Part_Number=ERJ-2RKF1500X, Package_Type=0402, Power=100, Tolerance=1%
R39 R67: library part 1000971, "RES 1.00M OHM 1/16W 1% 0402 SMD", Manufacturer=Yageo, Manufacturer_Part_Number=RC0402FR-071ML, Package_Type=0402, Power=63, Tolerance=1
R49 R70: library part 1000828, "RES 12.1K OHM 1/10W 1% 0402 SMD", Manufacturer="Panasonic - ECG", Manufacturer_Part_Number=ERJ-2RKF1212X, Package_Type=0402, Power=100, Tolerance=1%
R86: library part 1001153, "RES 27.0K OHM 1/16W 1% 0402 SMD", Manufacturer=Yageo, Manufacturer_Part_Number=RC0402FR-0727KL, Package_Type=0402, Tolerance=1%
R89: library part 1000174, "RES 15.0K OHM 1/10W 1% 0402 SMD", Manufacturer="Panasonic - ECG", Manufacturer_Part_Number=ERJ-2RKF1502X, Package_Type=0402, Power=10, Tolerance=1%
R94 R109 R110: library part 1001156, "RES 2.20K OHM 1/16W 1% 0402 SMD", Manufacturer=Yageo, Manufacturer_Part_Number=RC0402FR-072K2L, Package_Type=0402, Tolerance=1%
R104 R116 R119 R120 R121 R133: library part 1001158, "RES 120 OHM 1/16W 1% 0402 SMD", Manufacturer=Yageo, Manufacturer_Part_Number=RC0402FR-07120RL, Package_Type=0402, Tolerance=1%
R139 R140: library part 1000480, "RES 100K OHM 1/10W 1% 0402 SMD", Manufacturer="Panasonic - ECG", Manufacturer_Part_Number=ERJ-2RKF1003X, Package_Type=0402, Power=100, Tolerance=1%
R142: library part 1001916, "RES SMD 2 OHM 5% 1/10W 0603", Manufacturer="Panasonic - ECG", Manufacturer_Part_Number=ERJ-3GEYJ2R0V, Package_Type=0603, Power=100, Tolerance=1
R143: library part 1001518, "RES 53.6K OHM 1/10W 1% 0603 SMD", Manufacturer="Panasonic - ECG", Manufacturer_Part_Number=ERJ-3EKF5362V, Package_Type=0603
R144: library part 1001200, "RES 12.0K OHM 1/10W 1% 0603 SMD", Manufacturer=Yageo, Manufacturer_Part_Number=RC0603FR-0712KL, Package_Type=0603, Power=100, Tolerance=1
R148: library part 1001557, "RES 0.0 OHM 1/8W JUMP 0805 SMD", Manufacturer=Yageo, Manufacturer_Part_Number=RC0805JR-070RL, Package_Type=0805, Power=125
SW1 SW2: library part 1001124, "SWITCH TACTILE SPST-NO 0.05A 32V", Manufacturer=ITT, Package_Type=SMT
SW3: library part 1001500, "SWITCH DIP 2POS HALF PITCH 24V", Manufacturer="C&K Components", Package_Type=SMT
TP1 TP2: library part CAD0011, "TEST POINT 30mil PAD SMT", Package_Type=TP
U1: library part 1001177, "module, CCWMX6", Manufacturer=DIGI, Manufacturer_Part_Number=50001876-02, Package_Type=LGA
U2 U4: library part 1001179, "IC SWITCH SPDT SC88", Manufacturer="On Semiconductor", Package_Type=SOT363
U3 U11: library part 1001205, "MOSFET P-CH 20V 7.8A 6-MICROFET", Manufacturer="Fairchild Semiconductor", Package_Type=DFN
U5: library part 1001206, "TVS DIODE 5VWM 9.2VC SMB", Manufacturer="Vishay Semiconductors", Package_Type=SMB
U6: library part 1001160, "IC GATE NAND 2-INP HS LOG SC70-5", Manufacturer="Fairchild Semiconductor", Package_Type=SC70
U7: library part 1001857, "IC SW W/CTRL SLEW RATE 4TDFN", Manufacturer="Vishay Siliconix", Manufacturer_Part_Number=SIP32401ADNP-T1GE4, Package_Type=SON
U8 U9: library part 1001499, "IC RS232 3V-5.5V DRVR 28-TSSOP", Manufacturer="Texas Instruments", Package_Type=SOP
U10: library part 1001110, "IC TXRX ETHERNET 48-QFN", Manufacturer=Micrel, Package_Type=QFN
U12 U14: library part 1001143, "IC SW DISTRIBUTION 2CHAN 8SOIC", Manufacturer=Micrel, Manufacturer_Part_Number=MIC2026-1YM, Package_Type=SOIC
U13: library part 1001114, "4-PORT USB 2.0 HUB CTRLR 36VQFN", Manufacturer=SMSC, Package_Type=QFN
U15 U22: library part 1001163, "MOSFET P-CH 20V 3.7A SOT23-3", Manufacturer="Vishay Siliconix", Package_Type=SMT
U16: library part 1001125, "IC HDMI XMITTER PORT P/I 38TSSOP", Manufacturer="On Semiconductor", Package_Type=SOP
U17: library part 1001126, "IC AUDIO CODEC STEREO 32-QFN", Manufacturer="Freescale Semiconductor", Manufacturer_Part_Number=16051534, Package_Type=QFN
U18 U19: library part 1001129, "IC CAN TRANSCEIVER 3.3V 8-SOIC", Manufacturer="Texas Instruments", Package_Type=SOIC
U20 U21: library part 1001265, "TVS DIODE 5.5VWM 6SON", Manufacturer="Texas Instruments", Package_Type=SMT
U23: library part 1001907, "IC REG BUCK ADJ 3A SYNC", Manufacturer="Linear Technology", Manufacturer_Part_Number=MP2316GD, Package_Type=QFN
X1: library part 1001497, "SMCRY,25MHZ 50PPM 20PF RH100 EXT", Manufacturer=Raltron, Package_Type=SMT
X2: library part 1001134, "CRYSTAL 24MHZ 18PF SMD", Manufacturer=Aker, Manufacturer_Part_Number=C3E-24.000-18-3030-X-R, Package_Type=SMT

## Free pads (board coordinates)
  round 5.5 hole 3.2: 0(3,3) 0(3,69) 0(97,3) 0(97,69)
  rect 5.8x5.8 hole 2.6: 0(10.45,21.9) 0(10.45,46.1) 0(34.6,21.9) 0(34.6,46.1)

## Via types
v1: diameter 0.45, hole 0.2, Top Layer to Bottom Layer, 1473 vias

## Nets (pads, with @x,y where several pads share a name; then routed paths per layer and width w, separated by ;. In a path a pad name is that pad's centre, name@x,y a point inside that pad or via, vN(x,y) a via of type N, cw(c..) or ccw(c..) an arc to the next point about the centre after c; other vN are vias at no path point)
3V3: C5.2 C6.2 C7.2 C12.2 C13.2 C19.2 C21.2 C26.2 C27.2 C82.2 C99.2 C100.2 C105.2 C106.2 CAD1.1 D3.A J4.1 J7.4 J10.1 J17.20 J19.1 J21.37 J21.38 J28.3 J29.5 J30.5 J31.1 J33.20 J34.1 L2.1 L17.2 L28.1 P18.1 P18.2 P20.1 R7.2 R9.2 R10.2 R16.2 R22.2 R24.2 R25.2 R30.2 R31.2 R32.2 R33.2 R34.2 R36.2 R64.2 R65.2 R66.2 R68.2 R69.1 R75.1 R76.1 R78.1 R83.1 R88.1 R90.1 R93.2 R109.2 R110.2 R117.1 R118.1 R122.1 R127.1 R128.1 R132.2 R135.2 R139.1 R149.1 U1.P5 U1.Y9 U1.Y13 U2.5 U4.5 U6.5 U8.23 U8.26 U9.23 U9.26 U11.4 U11.8 U13.27 U16.2 U18.3 U19.3 U22.S | length 120.7
  Top Layer w0.25: v1(24.25,36.875) 24.25,37.625 24.375,37.75 L2.1@24.895,37.75 ; U8.26@26.375,59.805 26.375,58.275 26.863,57.787 v1(27.68,57.787) ; U8.23@28.325,59.805 28.3,59.83 28.4,59.93 v1(28.4,60.9) ; U9.26@36.575,61.65 v1(36.575,62.775) ; v1(38.525,60.525) U9.23@38.525,61.65 ; v1(39.75,65.75) J17.20@39.75,66.8 ; U1.P5@55.5,36.5 55.8,36.8 v1(56.5,36.8)
  Top Layer w0.3: P18.1@1.575,43 3.1,43 4.1,42 P18.2@5.225,42 v1(6.65,42) ; v1(7.55,41.1) 7.55,40.75 7.96,40.34 J10.1@8.868,40.34 ; J19.1@33.625,65.2 33.625,63.375 v1(33.65,63.35) ; v1(41.3,30.3) 41.645,29.955 R64.2@41.645,29.25 ; D3.A@55.075,13.15 55.975,13.15 56.75,12.375 v1(57.875,12.375) ; C82.2@57.96,10.625 v1(58.625,10.625) ; U1.Y9@63.5,24.5 64.25,23.75 v1(64.3,23.75) ; P20.1@69.7,70.425 73.225,70.425 74.54,69.11 C106.2@74.54,68.45 74.54,67.99 v1(74.3,67.75) ; U1.Y13@71.5,24.5 71.5,23.749 72.45,22.799 v1(72.45,22.5) ; v1(75.5,12.375) C12.2@75.5,13.21
  Top Layer w0.4: v1(25.75,25.85) 26.32,25.85 ; R66.2@26.32,25.275 26.32,25.85 ; R65.2@26.32,26.45 26.32,25.85 ; v1(32.2,37.4) 32.2,38.55 U11.8@32.4,38.75 U11.4@33.31,38.75 ; R127.1@38.52,63.6 38.525,63.595 U9.23@38.525,61.65 ; v1(71.625,13.25) C13.2@72.29,13.25
  Bottom Layer w0.125: v1(20.25,21.75) 20.655,22.155 R7.2@20.655,22.55 ; R68.2@24.895,36.86 25.455,36.3 26.7,36.3 28.25,34.75 U13.27@29.075,34.75 ; v1(41.45,57.5) 41.48,57.5 R22.2@42,56.98 ; v1(48.55,51.2) 49.28,51.2 R110.2@49.5,50.98 ; v1(93,49.2) 93.02,49.18 R117.1@93.02,48.5
  Bottom Layer w0.15: R9.2@21.2,58.82 23.1,58.82 R10.2@23.6,59.32 24.6,58.32 v1(24.6,58.3) ; R139.1@74.25,57.53 74.42,57.7 v1(74.95,57.7)
  Bottom Layer w0.2: R76.1@9.83,62.65 10.05,62.87 v1(10.05,63.85) ; R135.2@37.45,40.42 37.72,40.42 v1(38.2,40.9) ; R24.2@79.62,50.35 80.18,49.79 83.019,49.79 83.165,49.936 83.165,49.965 83.525,50.325 85.175,50.325 R83.1@85.4,50.1
  Bottom Layer w0.25: v1(24.25,36.875) R68.2@24.895,36.875 ; R69.1@24.895,35.75 R68.2@24.895,36.86 ; v1(25.05,41.45) 25.5,41 L17.2@25.5,39.85 ; C19.2@27.11,58.3 27.166,58.3 v1(27.68,57.787) ; C26.2@28.2,60.11 28.4,60.31 v1(28.4,60.9) ; C21.2@35.75,62.11 35.75,62.45 36.075,62.775 v1(36.575,62.775) 36.575,62.435 C27.2@36.9,62.11 ; v1(49.25,65.9) J33.20@49.25,66.8 ; v1(49.375,3.75) R90.1@49.375,4.395 ; v1(50.875,3.75) R88.1@50.875,4.395 ; v1(50.95,31.1) 51.02,31.03 R109.2@51.02,30.5 ; v1(72.45,22.5) R93.2@73.02,22.5 ; J21.37@72.5,66.8 v1(72.5,68.125) ; R78.1@72.58,65.1 v1(73.1,65.1) ; v1(73,65.875) J21.38@73,66.8 ; v1(84.7,60.85) 85.39,60.85 C99.2@85.5,60.96 85.932,60.96 86.297,61.325 86.697,61.325 87.012,61.01 U18.3@88.675,61.01 ; C100.2@86,53.19 86.055,53.135 v1(86.55,53.135) U19.3@87.8,53.135
  Bottom Layer w0.3: C105.2@5.2,41.99 6.64,41.99 v1(6.65,42) ; CAD1.1@11.535,40.24 12.14,40.24 12.3,40.4 v1(12.3,41.7) ; R149.1@17.18,34 v1(17.8,34) ; R118.1@32.35,62.4 32.65,62.4 33.6,63.35 v1(33.65,63.35) ; R75.1@43.75,19.73 v1(43.75,20.3) ; v1(57.875,6.525) U16.2@57.875,7.75 ; v1(65.5,10.55) 65.67,10.55 R30.2@66.05,10.93 ; v1(66.05,4.95) R32.2@66.05,5.47 ; R31.2@66.05,8.68 v1(66.05,9.2) ; v1(73.1,65.1) 73.62,65.1 R36.2@74.27,64.45 ; R25.2@75.28,50.4 R24.2@79.62,50.4 ; C7.2@75.5,18.04 75.99,18.04 v1(76.45,18.5) U4.5@77.4,18.5 ; C6.2@75.5,22.04 75.84,21.7 v1(76.15,21.7) 76.35,21.5 U2.5@77.4,21.5 ; C5.2@75.5,24.96 76.26,24.96 v1(76.45,25.15) U6.5@77.4,25.15 ; J7.4@75.75,5.1 v1(75.75,6.25) ; U22.S@80.35,29.15 80.92,29.72 R128.1@81.7,29.72 83.08,29.72 v1(83.45,29.35) 84.22,28.58 R16.2@84.22,28.5 ; R34.2@82.5,6.93 83.23,6.93 v1(83.25,6.95) ; R33.2@82.5,9.48 83.03,9.48 v1(83.05,9.5) ; R132.2@85.25,30.22 85.72,30.22 v1(86.35,30.85) ; v1(86.65,50) 86.55,50.1 R83.1@85.4,50.1 86.2,49.3 v1(87.5,49.3) ; v1(93,22.05) 93,22.91 R122.1@93.84,23.75
  Bottom Layer w0.4: J31.1@9.875,65.2 9.875,64.025 v1(10.05,63.85)
  other v1: 16.4,60.525 15.85,60.55 15.55,61.05
3V3_CODEC: C95.2 C96.2 L26.1 U17.20 U22.D | length 20.2
  Layer 8 w0.3: v1(64.75,25.4) 65.95,26.6 70.85,26.6 72.05,27.8 75.75,27.8 v1(77.34,29.39)
  Bottom Layer w0.2: L26.1@77.15,28.1 77.15,28.99 C96.2@76.75,29.39 v1(77.34,29.39) U22.D@78.05,30.1
  Bottom Layer w0.3: v1(64.75,25.4) 65.71,26.36 C95.2@65.71,26.5 66.157,26.5 66.407,26.25 U17.20@67.05,26.25
5V: C80.2 C81.2 J5.1 J21.39 J21.40 L35.1 L45.1 R12.2 R21.2 U1.F16 U16.1 | length 27.8
  Top Layer w0.3: v1(89.02,12.87) R12.2@89.02,13.5
  Top Layer w0.325: v1(76.7,52.7) 76.9,52.5 U1.F16@77.5,52.5
  Top Layer w0.7: L35.1@5.55,64.6 5.55,65.2 6.3,65.95 v1(6.65,65.95) v1(7.15,65.95)
  Layer 5 w0.5: v1(74.9,65.7) v1(74.55,65.35) 74.85,65.05 74.85,61.1 77.25,58.7 77.25,54.4 76.7,53.85 v1(76.7,52.7)
  Bottom Layer w0.25: v1@55.15,3.55 C80.2@55.15,4.65 ; C81.2@58.335,5.15 C81.2@58.335,5.25 58.335,5.86 v1(58.375,5.9) ; J21.39@73.5,66.8 v1(73.5,67.725) ; v1(74,65.875) J21.40@74,66.8
  Bottom Layer w0.3: v1(58.375,5.9) 58.375,6.258 58.4,6.283 58.4,7.725 U16.1@58.375,7.75
  Bottom Layer w0.325: v1(43.7,64.7) 43.7,63.95 R21.2@43.9,63.75 44.2,64.05 v1(44.2,64.7)
  Bottom Layer w0.5: v1(36.7,65.15) 37.05,65.15 v1(37.15,65.05) 37.4,64.8 L45.1@37.4,64.05
  other v1: 55.125,3.525
AGND: C94.1 C97.1 C98.1 D7.1 D8.1 D9.1 J22.1 L27.2 R91.1 R92.1 U17.4 U17.7 | length 13.7
  Top Layer w0.3: D7.1@68.175,13.25 v1(68.75,13.25) D9.1@69.325,13.25 ; v1(76.125,13.25) D8.1@76.7,13.25
  Top Layer w0.4: v1(67.125,4.75) v1(67.75,4.75) ; J22.1@67.7,2.8 J22.1@67.7,3.325 ; J22.1@67.75,2.8 v1(67.75,4.75) ; v1(68.375,4.75) v1(67.75,4.75)
  Bottom Layer w0.25: v1(70.375,17.375) R91.1@70.375,18.145 ; U17.7@71.95,25.25 72.5,25.25 v1(72.75,25) ; U17.4@71.95,26.75 73.25,26.75 C97.1@73.46,26.96 ; v1(72.75,17.375) R92.1@72.75,18.145 ; C97.1@73.5,26.96 73.96,26.96 v1(74.25,27.25)
  Bottom Layer w0.4: C94.1@65.875,22.96 66.24,22.96 v1(66.45,22.75) ; v1(74.25,27.25) 74.25,27.3 L27.2@75.15,28.2 75.5,27.85 C98.1@75.5,26.96
AUD_CLK: R1.2 U17.21 | length 43.2
  Layer 8 w0.125: v1(46.125,43.125) 45.625,43.625 45.625,48.5 46.15,49.025 v1(46.15,49.4)
  Layer 10 w0.125: v1(46.125,43.125) 46.658,43.125 48.163,41.621 48.163,35.226 48.125,35.188 48.125,33.25 50.875,30.5 51.5,30.5 54.75,27.25 57.375,27.25 57.875,27.75 59,27.75 60.375,29.125 63.625,29.125 63.875,29.375 64.5,29.375 65.5,28.375 v1(65.5,27.625)
  Bottom Layer w0.125: v1(46.15,49.4) 46.525,49.4 47.02,49.895 R1.2@47.02,50.5 ; v1(65.5,27.625) 66.125,27 66.313,27 66.563,26.75 U17.21@67.05,26.75
AUD_HP_DET: D9.2 J22.5 R93.1 U1.J24 | length 70.5
  Top Layer w0.125: J22.5@67.725,6.125 v1(69,6.125) ; D9.2@70.425,13.25 v1(71,13.25) ; U1.J24@93.5,46.5 94.15,46.5 v1(94.5,46.85)
  Layer 5 w0.125: v1(71,13.25) 71,13.575 74.25,16.825 74.25,18.75 73.75,19.25 73.75,21.625 v1(74.625,22.5)
  Layer 10 w0.125: v1(74.625,22.5) 78.9,22.5 79.837,23.437 80.671,23.437 80.896,23.663 95.413,23.663 97.15,25.4 97.15,32.4 97.8,33.05 97.8,45.05 96,46.85 v1(94.5,46.85)
  Layer 3 w0.125: v1(69,6.125) 71,8.125 v1(71,13.25)
  Bottom Layer w0.125: R93.1@73.98,22.5 v1(74.625,22.5)
AUD_I2C_SCL: R114.2 U17.29 | length 28.9
  Layer 10 w0.125: v1(47.8,31.35) 47.8,31.075 48.25,30.625 49.875,30.625 52.875,27.625 53.375,27.625 54.3,26.7 59.775,26.7 60.312,26.163 60.975,26.163 62.487,27.675 64.675,27.675 65.15,27.2 65.658,27.2 65.708,27.25 68.333,27.25 69,27.917 v1(69,29.8)
  Bottom Layer w0.125: R114.2@47.02,30.625 47.745,31.35 v1(47.8,31.35) ; v1(69,29.8) 69.317,29.8 69.75,29.367 U17.29@69.75,28.95
AUD_I2C_SDA: R115.2 U17.27 | length 48.8
  Layer 10 w0.125: v1(46.75,46) 46.542,46 45.712,45.171 45.712,39.163 47.85,37.025 47.85,36.3 47.913,36.237 47.913,35.329 47.85,35.267 47.85,33.35 47.387,32.887 47.387,30.688 47.7,30.375 49.625,30.375 52.25,27.75 52.25,27.25 53.25,26.25 55.425,26.25 55.625,26.45 59.25,26.45 59.975,25.725 59.975,25.125 60.475,24.625 61.775,24.625 63.213,26.063 65.113,26.063 65.85,26.8 68.4,26.8 69.45,27.85 69.45,29.667 69.437,29.679 69.437,29.946 69.171,30.213 68.829,30.213 68.4,29.783 v1(68.4,29.75)
  Bottom Layer w0.125: v1(46.75,46) R115.2@47.48,46 ; v1(68.4,29.75) 68.75,29.4 U17.27@68.75,28.95
AUD_PWR_EN: Q4.G R132.1 U1.V15 | length 11.4
  Top Layer w0.125: U1.V15@75.5,28.5 77.15,30.15 80.4,30.15 v1(81.6,31.35)
  Bottom Layer w0.125: v1(81.6,31.35) 82.3,31.35 82.813,31.863 83.337,31.863 83.8,31.4 Q4.G@84.09,31.4 85.03,31.4 R132.1@85.25,31.18
AUD_RXD: U1.M5 U17.25 | length 19.8
  Top Layer w0.125: U1.M5@55.5,40.5 v1(56.25,40.125)
  Layer 10 w0.125: v1(56.25,40.125) 56.458,40.125 61.663,34.921 61.663,34.879 65.104,31.438 67.562,31.438 68.113,30.887 68.113,30.399 66.875,29.162 v1(66.875,29.125)
  Bottom Layer w0.125: v1(66.875,29.125) 67.05,28.95 U17.25@67.75,28.95
AUD_TXC: U1.B7 U17.24 | length 38
  Top Layer w0.125: v1(59.5,59.75) U1.B7@59.5,60.5
  Layer 8 w0.125: v1(62.25,59.025) 61.95,58.725 61.95,50.454 62.8,49.604 62.8,31.95 v1(66.375,28.375)
  Layer 5 w0.125: v1(59.5,59.75) 59.5,59.017 60.029,58.487 60.437,58.487 60.5,58.55 61.775,58.55 v1(62.25,59.025)
  Bottom Layer w0.125: v1(66.375,28.375) 66.5,28.25 U17.24@67.05,28.25
AUD_TXD: U1.C7 U17.26 | length 34.4
  Top Layer w0.125: U1.C7@59.5,58.5 v1(60.75,58.125)
  Layer 5 w0.125: v1(60.75,58.125) 61.987,56.888 61.987,52.813 63.737,51.063 63.737,32.451 65.188,31 66.333,31 v1(67,30.333)
  Bottom Layer w0.125: v1(67,30.333) 67.217,30.333 68.25,29.3 U17.26@68.25,28.95
AUD_TXFS: U1.C5 U17.23 | length 38.7
  Top Layer w0.125: U1.C5@55.5,58.5 56.375,59.125
  Layer 5 w0.125: v1(56.625,59.125) 59,59.125 61.737,56.388 61.737,51.714 62.509,50.942 62.558,50.942 63.237,50.263 63.237,31.176 65.43,28.983 65.43,28.445 v1(66.125,27.75)
  Bottom Layer w0.125: v1(66.125,27.75) U17.23@67.05,27.75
